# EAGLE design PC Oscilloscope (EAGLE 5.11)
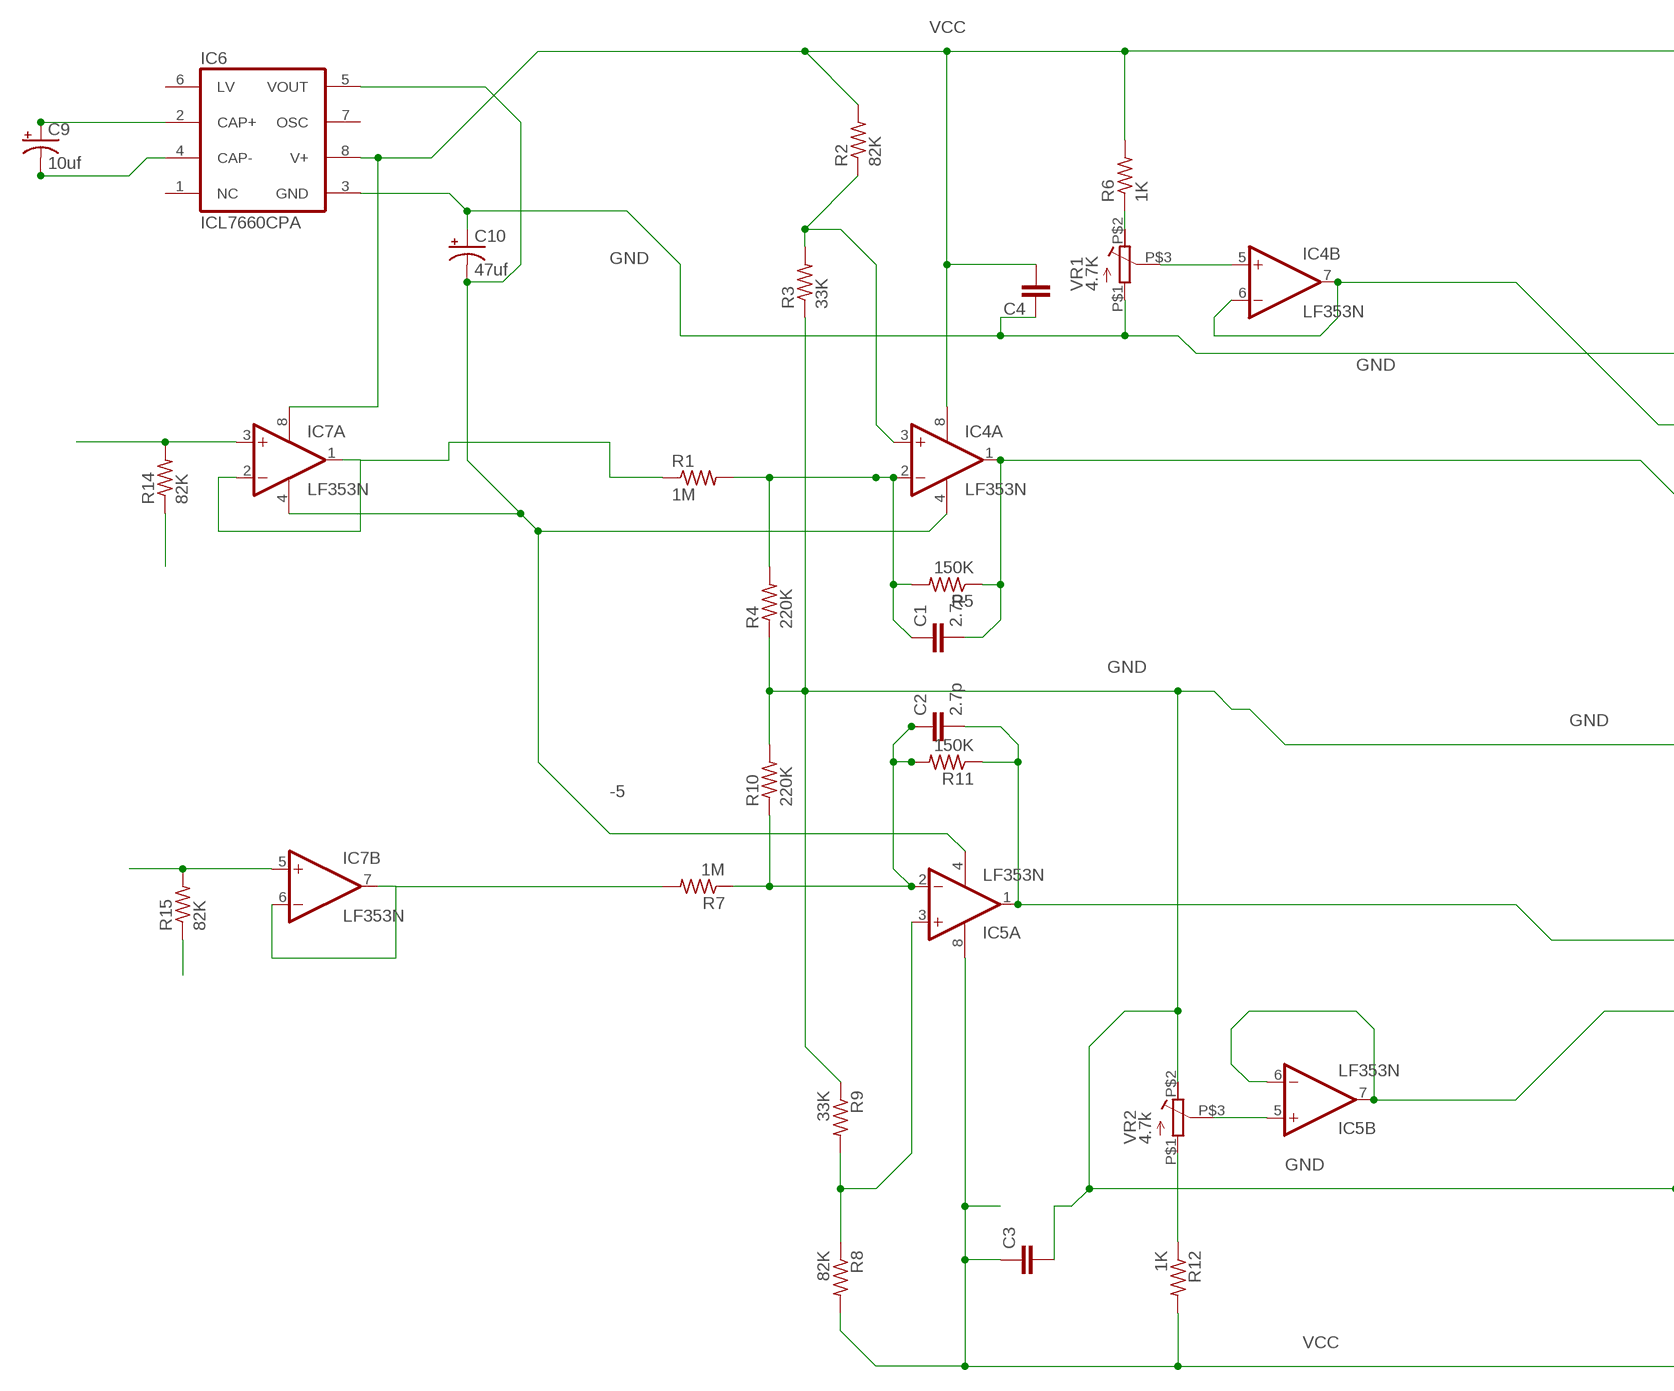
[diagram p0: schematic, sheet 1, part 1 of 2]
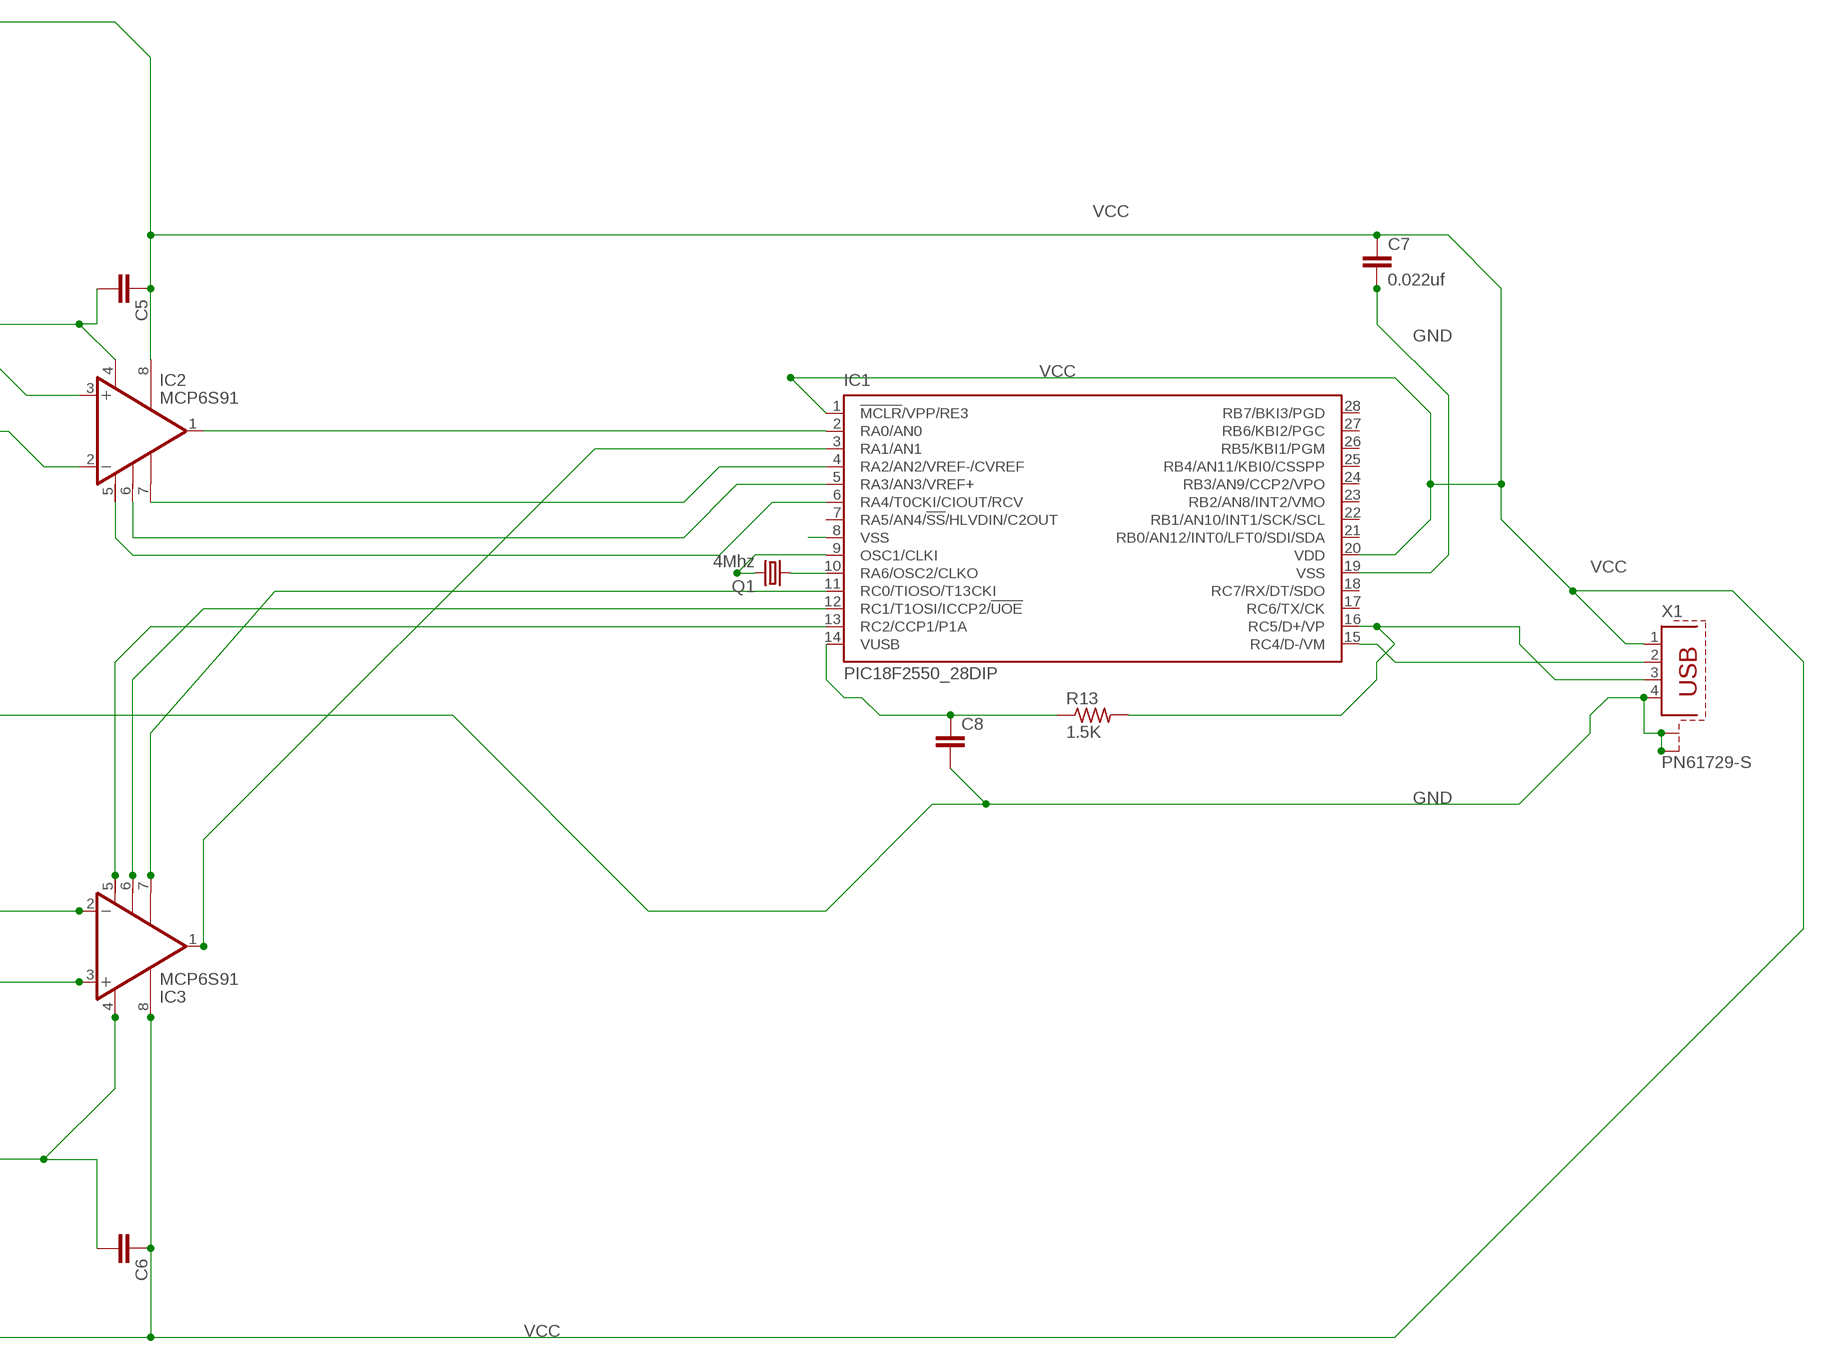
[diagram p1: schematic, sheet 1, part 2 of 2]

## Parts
C1  2.7p  C2,5-3  [C2.5-3]
C2  2.7p  C2,5-3  [C2.5-3]
C3  C7.5/5  [C7.5B5]
C4  C7.5/5  [C7.5B5]
C5  C7.5/5  [C7.5B5]
C6  C7.5/5  [C7.5B5]
C7  0.022uf  C2,5-3  [C2.5-3]
C8  C5/2.5  [C5B2.5]
C9  10uf  CPOL-USE2.5-5  [E2,5-5]
C10  47uf  CPOL-USE2.5-5  [E2,5-5]
IC1  PIC18F2550_28DIP  [DIL28-3]
IC2  MCP6S91  MCP6S  [DIL8]
IC3  MCP6S91  MCP6S  [DIL8]
IC4  LF353N  [DIL08]
IC5  LF353N  [DIL08]
IC6  ICL7660CPA  [DIL08]
IC7  LF353N  [DIL08]
Q1  4Mhz  CRYSTALHC49S  [HC49/S]
R1  1M  R-US_0207/10  [0207/10]
R2  82K  R-US_0207/10  [0207/10]
R3  33K  R-US_0207/10  [0207/10]
R4  220K  R-US_0207/10  [0207/10]
R5  150K  R-US_0207/10  [0207/10]
R6  1K  R-US_0207/10  [0207/10]
R7  1M  R-US_0207/10  [0207/10]
R8  82K  R-US_0207/10  [0207/10]
R9  33K  R-US_0207/10  [0207/10]
R10  220K  R-US_0207/10  [0207/10]
R11  150K  R-US_0207/10  [0207/10]
R12  1K  R-US_0207/10  [0207/10]
R13  1.5K  R-US_0207/10  [0207/10]
R14  82K  R-US_0207/10  [0207/10]
R15  82K  R-US_0207/10  [0207/10]
VR1  4.7K  VARIABLE_RESISTOR  [VAR_RES]
VR2  4.7k  VARIABLE_RESISTOR  [VAR_RES]
X1  PN61729-S  [PN61729-S]

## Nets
-5: C10.- IC4.4(P:V-) IC5.4(P:V-) IC6.5(VOUT) IC7.4(P:V-)
GND: C3.2 C4.1 C5.2 C6.2 C7.2 C8.2 C10.+ IC1.8(VSS) IC1.19(VSS) IC2.4(VSS) IC3.4(VSS) IC6.3(GND) R3.1 R4.1 R9.1 R10.2 R14.1 R15.1 VR1.P$1 VR2.P$2 X1.4 X1.S1 X1.S2
N$1: C2.1 IC5.2(A:-IN) R7.1 R10.1 R11.2
N$2: C2.2 IC3.2(IN) IC5.1(A:OUT) R11.1
N$3: IC5.3(A:+IN) R8.1 R9.2
N$6: C1.1 IC4.2(A:-IN) R1.2 R4.2 R5.2
N$7: C1.2 IC2.2(IN) IC4.1(A:OUT) R5.1
N$9: IC4.3(A:+IN) R2.1 R3.2
N$10: R6.1 VR1.P$2
N$11: IC3.3(REF) IC5.6(B:-IN) IC5.7(B:OUT)
N$13: C9.+ IC6.2(CAP+)
N$14: C9.- IC6.4(CAP-)
N$15: IC4.5(B:+IN) VR1.P$3
N$16: IC2.3(REF) IC4.6(B:-IN) IC4.7(B:OUT)
N$19: R12.1 VR2.P$1
N$20: IC5.5(B:+IN) VR2.P$3
N$21: IC1.10(RA6/OSC2/CLKO) Q1.1
N$23: IC1.2(RA0/AN0) IC2.1(OUT)
N$24: IC1.4(RA2/AN2/VREF-/CVREF) IC2.7(SCK)
N$25: IC1.5(RA3/AN3/VREF+) IC2.6(SI)
N$26: IC1.6(RA4/T0CKI/CIOUT/RCV) IC2.5(CS)
N$27: IC1.13(RC2/CCP1/P1A) IC3.5(CS)
N$28: IC1.12(RC1/T1OSI/ICCP2/!UOE) IC3.6(SI)
N$29: IC1.11(RC0/TIOSO/T13CKI) IC3.7(SCK)
N$30: IC1.3(RA1/AN1) IC3.1(OUT)
N$31: IC1.9(OSC1/CLKI) Q1.2
N$33: C8.1 IC1.14(VUSB) R13.1
N$34: IC1.16(RC5/D+/VP) R13.2 X1.3
N$35: IC1.15(RC4/D-/VM) X1.2
N$41: IC7.3(A:+IN) R14.2
N$42: IC7.1(A:OUT) IC7.2(A:-IN) R1.1
N$43: IC7.5(B:+IN) R15.2
N$44: IC7.6(B:-IN) IC7.7(B:OUT) R7.2
VCC: C3.1 C4.2 C5.1 C6.1 C7.1 IC1.1(!MCLR!/VPP/RE3) IC1.20(VDD) IC2.8(VDD) IC3.8(VDD) IC4.8(P:V+) IC5.8(P:V+) IC6.8(V+) IC7.8(P:V+) R2.2 R6.2 R8.2 R12.2 X1.1
Unconnected: IC1.7(RA5/AN4/!SS!/HLVDIN/C2OUT) IC1.17(RC6/TX/CK) IC1.18(RC7/RX/DT/SDO) IC1.21(RB0/AN12/INT0/LFT0/SDI/SDA) IC1.22(RB1/AN10/INT1/SCK/SCL) IC1.23(RB2/AN8/INT2/VMO) IC1.24(RB3/AN9/CCP2/VPO) IC1.25(RB4/AN11/KBI0/CSSPP) IC1.26(RB5/KBI1/PGM) IC1.27(RB6/KBI2/PGC) IC1.28(RB7/BKI3/PGD) IC6.1(NC) IC6.6(LV) IC6.7(OSC)

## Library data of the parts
C1-C8 = capacitor-wima:C: CAPACITOR
C9 C10 = rcl:CPOL-US: POLARIZED CAPACITOR, American symbol
IC1 = microchip:PIC18F2*_28: USB Microcontrollers with nanoWatt Technology High-Performance, Enhanced Flash, 28/40/44-Pin, Source: http://ww1.microchip.com/downloads/en/devicedoc/39632c.pdf; MF: MICROCHIP; MPN: PIC18F2550-I/SP; OC_FARNELL: 1523822; OC_NEWARK: 80K6054
IC2 IC3 = microchip:MCP6S**
IC4 IC5 IC7 = linear:LF353: OP AMP
IC6 = maxim:ICL7660CPA: VOLTAGE CONVERTER; MF: INTERSIL; MPN: ICL7660CPA; OC_FARNELL: 1018170; OC_NEWARK: 06F7441
Q1 = crystal:CRYSTAL: CRYSTAL; OC_FARNELL: 1667008; OC_NEWARK: unknown
R1-R15 = rcl:R-US_: RESISTOR, American symbol
VR1 VR2 = mycustom:VARIABLE_RESISTOR: Variable Resistor A Gernal purpose varible resistor
X1 = con-berg:PN61729-S: BERG USB connector; OC_FARNELL: unknown; OC_NEWARK: unknown

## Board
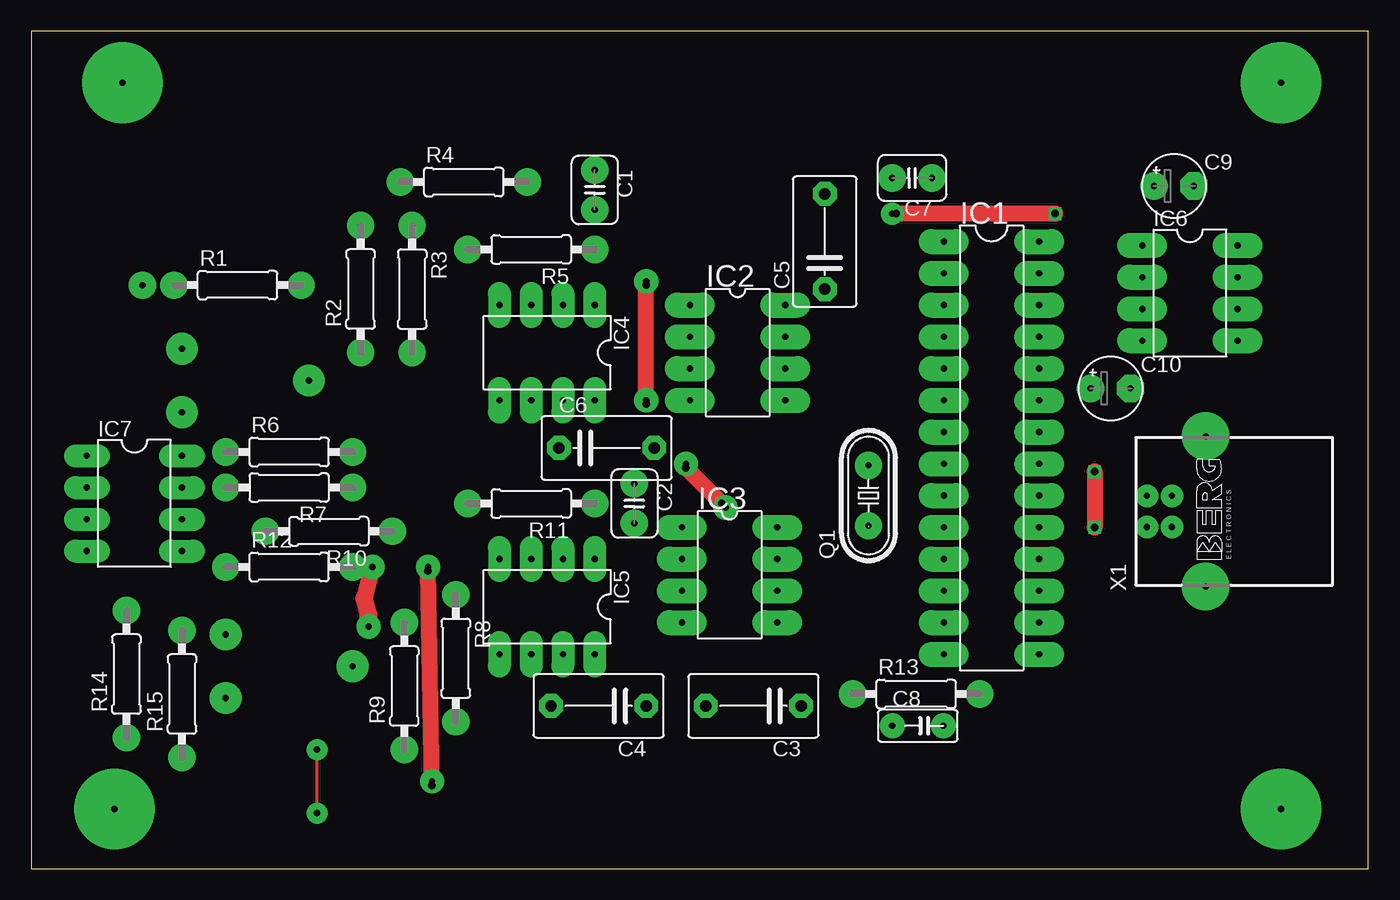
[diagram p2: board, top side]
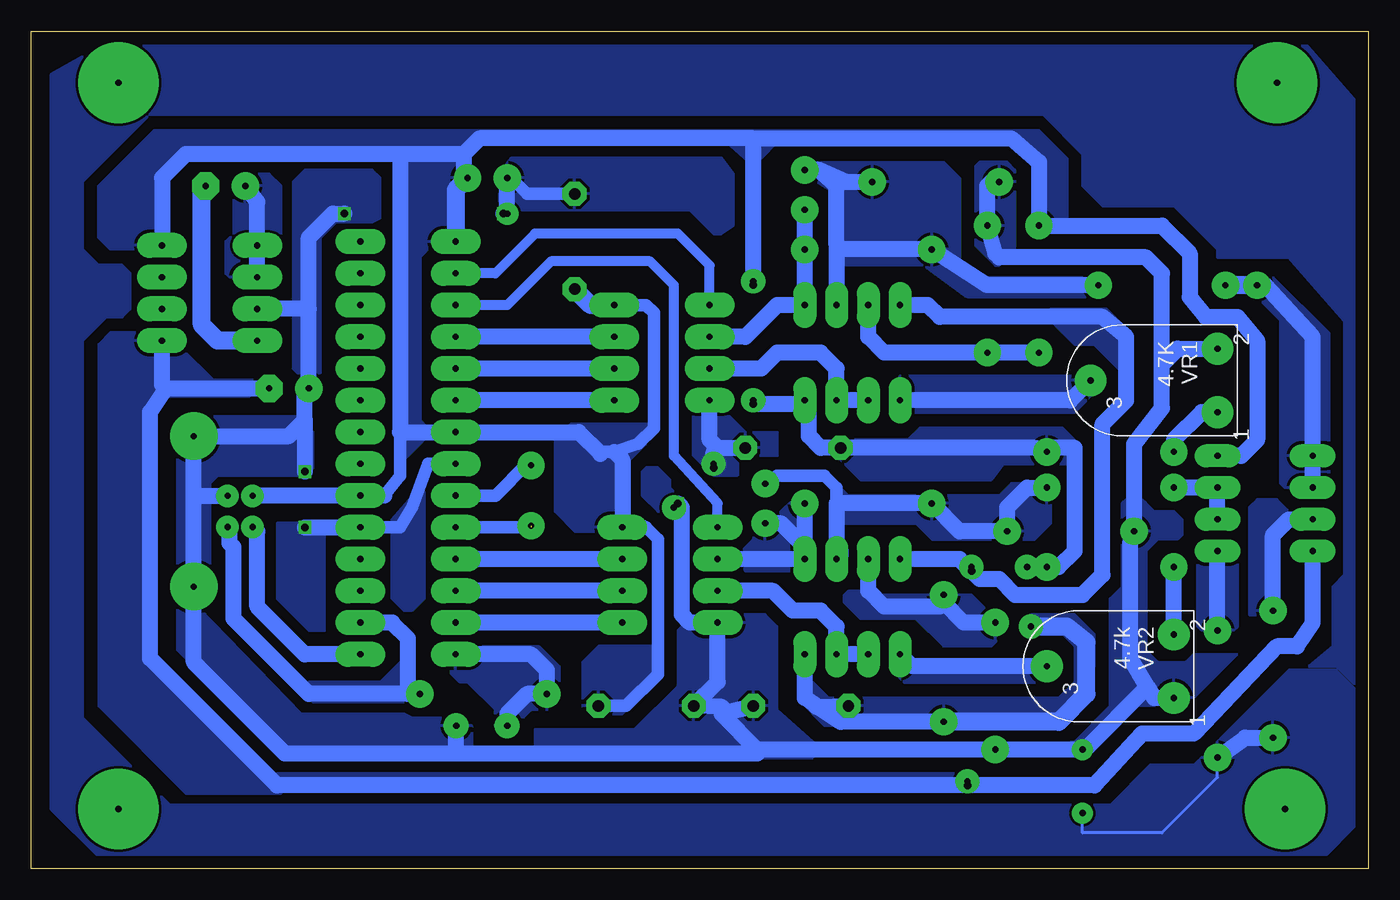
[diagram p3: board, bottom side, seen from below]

Size 106.98 x 66.98 mm. Coordinates in mm from the lower left corner, seen from the top.
Outline: 0,0 106.98,0 106.98,66.98 0,66.98 0,0
Copper layers (1*16): Top 0.035mm / dielectric 1.5mm / Bottom 0.035mm
Design rules "default": minimum track width 10mil, minimum drill 24mil, track to track 8mil, track to pad 8mil, pad to pad 8mil, via to via 8mil, smd to smd 8mil, copper to edge 40mil, drill to drill 8mil, minimum pad ring 10mil, minimum via ring 8mil, stop-mask expansion 4mil, vias tented up to drill 0mil, thermal gap 10mil

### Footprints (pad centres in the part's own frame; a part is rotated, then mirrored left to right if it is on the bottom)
C2.5-3 = drill 0.5 pad 2.184 round: 1 -1.587,0; 2 1.587,0
C7.5B5 = drill 0.914 pad 1.905 octagon: 1 -3.81,0; 2 3.81,0
C5B2.5 = drill 0.5 pad 2 round: 1 -2.54,0; 2 1.54,0
E2,5-5 = drill 0.5 pad 2.184 round: + -1.587,0 | drill 0.5 pad 2.184 octagon: - 1.587,0
DIL28-3 = drill 0.5 pad 2 long: 1 -16.51,-3.81; 2 -13.97,-3.81; 3 -11.43,-3.81; 4 -8.89,-3.81; 5 -6.35,-3.81; 6 -3.81,-3.81; 7 -1.27,-3.81; 8 1.27,-3.81; 9 3.81,-3.81; 10 6.35,-3.81; 11 8.89,-3.81; 12 11.43,-3.81; 13 13.97,-3.81; 14 16.51,-3.81; 15 16.51,3.81; 16 13.97,3.81; 17 11.43,3.81; 18 8.89,3.81; 19 6.35,3.81; 20 3.81,3.81; 21 1.27,3.81; 22 -1.27,3.81; 23 -3.81,3.81; 24 -6.35,3.81; 25 -8.89,3.81; 26 -11.43,3.81; 27 -13.97,3.81; 28 -16.51,3.81
DIL8 = drill 0.5 pad 2 long: 1 -3.81,-3.81; 2 -1.27,-3.81; 3 1.27,-3.81; 4 3.81,-3.81; 5 3.81,3.81; 6 1.27,3.81; 7 -1.27,3.81; 8 -3.81,3.81
DIL08 = drill 0.5 pad 1.85 long: 1 -3.81,-3.81; 2 -1.27,-3.81; 3 1.27,-3.81; 4 3.81,-3.81; 5 3.81,3.81; 6 1.27,3.81; 7 -1.27,3.81; 8 -3.81,3.81
DIL08' = drill 0.5 pad 2 long: 1 -3.81,-3.81; 2 -1.27,-3.81; 3 1.27,-3.81; 4 3.81,-3.81; 5 3.81,3.81; 6 1.27,3.81; 7 -1.27,3.81; 8 -3.81,3.81
HC49/S = drill 0.5 pad 2.184 round: 1 -2.413,0; 2 2.413,0
0207/10 = drill 0.5 pad 2.184 round: 1 -5.08,0; 2 5.08,0
VAR_RES = drill 0.5 pad 2.54 round: P$1 -2.54,3.81; P$2 2.54,3.81; P$3 0,-6.35
PN61729-S = drill 0.5 pad 1.8 round: 1 1.25,4.71; 2 -1.25,4.71; 3 -1.25,2.71; 4 1.25,2.71 | drill 0.5 pad 3.81 round: S1 -6.02,0; S2 6.02,0

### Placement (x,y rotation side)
C1  45.09,54.29 270 top
C2  48.26,29.21 270 top
C3  57.78,13.02 180 top
C4  45.4,13.02 180 top
C5  63.5,50.16 90 top
C6  46.04,33.66 0 top
C7  70.48,55.24 180 top
C8  71.44,11.43 0 top
C9  91.44,54.61 0 top
C10  86.36,38.42 0 top
IC1  76.83,33.66 270 top
IC2  56.52,41.27 270 top
IC3  55.88,23.5 270 top
IC4  41.27,41.27 180 top
IC5  41.27,20.95 180 top
IC6  ICL7660CPA  [DIL08']  92.71,46.04 270 top
IC7  8.26,29.21 270 top
Q1  66.99,29.84 90 top
R1  16.51,46.67 0 top
R2  26.35,46.35 90 top
R3  30.48,46.35 270 top
R4  34.61,54.93 0 top
R5  40.01,49.53 180 top
R6  20.64,33.34 0 top
R7  20.64,30.48 180 top
R8  33.97,16.83 270 top
R9  29.84,14.61 90 top
R10  23.81,26.99 180 top
R11  40.01,29.21 180 top
R12  20.64,24.13 0 top
R13  70.8,13.97 0 top
R14  7.62,15.56 90 top
R15  12.06,13.97 90 top
VR1  15.88,39.05 270 bottom
VR2  19.37,16.19 270 bottom
X1  93.98,28.57 90 top

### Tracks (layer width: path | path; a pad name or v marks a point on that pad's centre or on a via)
-5  (via drill 0.6)
  Top 1.27: v32.07,6.67 v31.75,23.81
  Bottom 1.27: IC4.4 35.24,45.09 34.29,44.13 21.27,44.13 19.37,42.55 19.37,37.47 21.27,35.56 21.27,23.5 22.86,21.91 28.26,21.91 29.53,23.18 31.11,23.18 v31.75,23.81 | v31.75,23.81 32.7,24.77 | 32.7,24.77 IC5.4 | v31.75,23.81 32.7,24.77 | 96.2,38.42 C10.- | 96.2,38.42 97.47,36.51 97.47,16.83 87.31,6.67 v32.07,6.67 21.91,6.67 18.1,10.79 13.97,10.79 7.3,17.78 5.71,17.78 4.45,19.68 IC7.4 | IC6.5 96.52,38.73 96.2,38.42
  pour Bottom: 89.22,39.05 92.39,39.05 94.93,41.59 94.93,42.55 95.25,42.86 100.65,42.86 101.6,41.91 101.6,13.02 94.61,6.03 87,6.03 86.36,6.67 87,6.67 97.47,17.14 97.47,37.47 97.16,37.78 89.53,37.78 89.22,38.1
  pour Bottom: 87.31,7.62 33.02,7.62 31.75,6.35 87,6.35 87.95,7.3
  pour Bottom: 19.05,40.01 20,40.01 21.91,41.91 23.5,41.91 25.4,43.81 25.4,44.77 20.95,44.77 19.05,42.86
GND  (via drill 0.5 pad 1.68, 0.5 pad 1.93, 0.6)
  Top 0.254: v22.86,4.45 v22.86,9.53
  Top 1.27: v81.92,52.39 v69.22,52.39 | v55.24,29.21 v52.39,32.07 | v85.09,31.75 v85.09,27.3
  Bottom 0.254: VR2.P$2 18.1,13.65 18.41,13.97 v22.86,9.53 | v22.86,4.45 22.86,2.86 16.51,2.86 12.06,7.3 R15.1
  Bottom 1.016: IC1.8 75.25,32.38 76.52,28.89 77.47,27.3 IC1.19 | C7.2 68.58,55.24 67.31,53.98 C5.2
  Bottom 1.27: VR2.P$2 17.14,13.65 17.68,14.54 | 17.68,14.54 19.05,16.83 19.05,26.04 R10.2 18.73,33.97 16.51,36.83 16.51,40.32 | 48.58,9.53 R9.1 v22.86,9.53 22.69,9.53 17.68,14.54 | 48.58,9.53 48.9,9.53 51.75,12.38 51.3,12.49 | R4.1 30.16,54.93 30.48,54.61 R3.1 29.84,49.21 29.53,48.9 17.78,48.9 16.51,47.62 16.51,40.32 | VR1.P$1 15.24,41.59 16.51,40.32 | X1.S1 | X1.S1 93.98,16.51 86.68,9.21 73.03,9.21 | 73.03,9.21 48.9,9.21 48.58,9.53 | 51.3,12.49 C4.1 | C7.2 68.9,52.7 v69.22,52.39 | IC3.4 53.66,19.68 | IC3.4 52.07,14.92 C3.2 51.75,12.94 51.3,12.49 | IC2.4 52.7,34.29 52.07,33.66 | 52.07,33.66 C6.2 49.85,33.34 | IC3.4 54.29,19.68 54.93,20.32 54.93,28.89 v55.24,29.21 | v52.39,32.07 v52.39,32.38 52.39,33.34 52.07,33.66 | C8.2 72.98,9.26 73.03,9.21 | v81.92,52.39 82.87,52.39 84.77,50.48 84.77,44.77 | 84.77,44.77 IC6.3 | 84.77,44.77 C10.+ 85.09,38.1 85.09,35.88 | X1.S1 93.98,29.84 | 93.98,29.84 X1.S2 86.37,34.59 85.09,35.88 | v85.09,27.3 IC1.19 | 85.09,35.88 v85.09,31.75 | X1.4 93.96,29.82 93.98,29.84 | R14.1 9.84,10.48 R15.1
  pour Bottom: 82.87,27.62 87.31,27.62 87.31,21.59 84.77,19.05 83.5,19.05 83.5,26.99
  pour Bottom: 50.8,55.56 51.75,56.83 68.58,56.83 69.53,55.56 69.53,53.34 68.9,52.7 54.29,52.7 52.39,50.8 51.75,50.8 50.8,51.44
  pour Bottom: 48.26,20.32 53.98,20.32 55.24,19.05 55.24,14.61 58.74,11.11 66.67,11.11 66.67,8.89 44.45,8.89 44.45,10.16 47.31,12.7 47.31,19.37
  pour Bottom: 53.98,37.47 52.39,37.47 49.85,34.92 47.31,34.92 47.31,33.02 50.16,33.02 50.48,32.7 50.48,31.43 52.39,31.43 53.98,33.02
  pour Bottom: 75.56,30.16 75.56,21.59 76.52,20.64 77.15,20.64 78.11,21.59 78.11,27.94 76.2,30.16
  pour Bottom: 93.34,21.91 93.66,20.95 85.41,12.38 77.15,12.38 76.52,12.06 72.39,12.06 71.75,11.43 71.75,9.53 72.39,8.89 87,8.89 94.3,16.19 94.3,16.51 95.25,17.46 95.25,35.56 94.61,36.2 85.72,36.2 84.45,34.92 84.45,32.07 85.09,31.43 92.08,31.43 92.71,30.8 92.71,22.54
  pour Bottom: 79.06,52.07 79.06,55.24 79.69,55.88 85.09,55.88 86.04,54.93 86.04,40.01 85.09,39.05 84.45,39.05 83.82,39.69 83.82,50.48 82.55,51.75 79.69,51.75
  pour Bottom: 28.89,56.52 31.11,56.52 31.43,56.2 31.43,49.85 29.84,48.26 29.53,48.26 28.26,49.53 28.26,55.88
  pour Bottom: 2.54,15.88 6.35,15.88 13.97,8.26 17.46,8.26 20.64,5.08 95.89,5.08 102.87,12.06 102.87,42.23 100.97,44.13 99.69,44.13 99.06,44.77 99.06,47.62 99.69,48.26 101.6,48.26 102.87,49.53 102.87,54.93 97.47,60.33 26.04,60.33 22.86,57.15 22.86,54.61 21.27,53.02 15.56,53.02 12.06,49.53 12.06,48.9 6.35,48.9 1.91,43.81 1.91,23.5 2.86,22.54 2.86,17.78 4.76,16.19 2.54,16.19 0.95,14.61 0.32,14.61 0.64,60.96 5.08,66.04 100.97,66.04 105.41,63.5 105.41,4.76 101.6,0.95 3.49,0.95 0.95,3.49 0.95,14.29
  pour Bottom: 18.73,29.53 18.1,29.53 17.78,29.21 17.46,28.89 17.14,28.57 15.56,28.57 14.92,27.94 14.92,26.67 15.24,26.35 16.83,26.35 17.78,25.4 17.78,17.46 16.83,16.51 14.92,16.51 14.29,15.88 14.29,13.34 14.61,13.02 18.41,13.02 21.91,9.53 23.18,9.53 23.81,10.16 23.5,10.16 20.64,13.02 20.64,21.59 19.68,22.54 19.68,29.21 19.37,29.53
  pour Bottom: 17.14,16.51 14.61,16.51 13.97,17.14 10.48,17.14 14.61,13.02 17.46,13.02
N$1
  Bottom 1.016: 47.94,30.8 47.31,31.43 43.5,31.43 42.55,30.48 42.55,29.21
  Bottom 1.27: R7.1 27.3,30.48 28.89,28.89 R10.1 32.7,26.99 R11.2 42.55,29.21 42.55,25.72 42.23,25.4 42.23,25.08 IC5.2 | 47.94,30.8 C2.1
  pour Bottom: 26.04,30.8 28.57,30.8 29.53,29.84 41.59,29.84 42.23,30.48 42.55,30.48 42.86,30.16 42.86,27.94 42.55,27.62 36.2,27.62 34.92,26.35 26.67,26.35 25.4,27.62 25.4,30.16
N$2
  Bottom 1.27: 45.09,25.72 IC5.1 IC3.2 | 45.09,25.72 R11.1 | C2.2 46.99,27.62 45.09,25.72
  pour Bottom: 45.4,29.84 45.72,29.84 47.31,28.26 48.9,28.26 49.21,27.94 49.21,26.35 50.16,25.4 50.16,24.13 49.85,23.81 45.09,23.81 45.09,29.21 44.77,29.53
N$3
  Bottom 1.27: 33.97,21.27 R8.1 | 33.97,21.27 32.38,19.68 R9.2 | IC5.3 40.01,22.23 38.73,20.95 34.29,20.95 33.97,21.27
  pour Bottom: 39.05,21.91 31.75,21.91 29.84,20 29.84,18.1 30.16,17.78 33.97,17.78 36.2,20 40.64,20 41.91,21.27 41.91,21.91 41.59,22.23 40.32,22.23
N$4  (via drill 0.5 pad 1.68)
  other vias: 22.86,4.45
N$5  (via drill 0.5 pad 1.93)
  other vias: 32.07,6.99
N$6
  Bottom 1.27: 42.55,49.85 IC4.2 | 42.55,49.85 42.55,54.61 44.05,55.93 | 44.05,55.93 C1.1 | 42.55,49.85 42.23,49.53 R5.2 30.48,46.67 R1.2 | R4.2 41.78,54.93 44.05,55.93
  pour Bottom: 45.4,56.52 33.97,56.52 32.7,55.24 32.7,48.58 31.43,47.31 21.91,47.31 21.91,45.72 32.07,45.72 35.56,48.26 42.23,48.26 42.55,48.58 42.55,53.98 45.09,55.56 45.72,55.56 45.72,56.2
N$7
  Bottom 1.27: IC2.2 49.85,42.55 47.31,45.09 IC4.1 R5.1 C1.2
N$8  (via drill 0.5 pad 2.18)
  other vias: 8.89,46.67
N$9
  Bottom 1.27: R2.1 R3.2 38.73,41.27 40.01,42.55 IC4.3
N$10
  Bottom 1.27: VR1.P$2 13.34,36.51 15.56,34.29 R6.1
N$11
  Bottom 1.27: IC5.6 IC5.7 42.55,19.37 43.81,20.64 46.04,20.64 47.62,22.23 IC3.3
N$12  (via drill 0.5 pad 1.78)
  other vias: 68.9,52.39
N$13
  Bottom 1.27: IC6.2 88.9,53.34 C9.+
  pour Bottom: 87.95,55.56 90.49,55.56 90.81,55.24 90.81,50.8 91.44,50.16 91.44,47.62 90.49,46.67 87.63,46.67 87,47.31 87,54.61
N$14
  Bottom 1.422: IC6.4 92.08,42.23 93.34,43.5 93.34,54.61 C9.-
N$15
  Bottom 1.27: VR1.P$3 23.81,37.47 IC4.5
  pour Bottom: 22.54,39.37 37.47,39.37 37.78,39.05 37.78,36.83 37.47,36.51 23.5,36.51 21.59,38.42
N$16
  Bottom 1.27: 53.02,39.69 IC2.3 48.58,40.01 47.31,41.27 43.81,41.27 42.55,40.01 IC4.7 IC4.6
N$17  (via drill 0.5 pad 1.93)
  other vias: 31.75,24.13
N$18  (via drill 0.5 pad 1.93)
  other vias: 55.56,28.89
N$19
  Bottom 1.27: VR2.P$1 R12.1
N$20
  Bottom 1.27: VR2.P$3 36.51,16.19 IC5.5
  pour Bottom: 25.72,16.51 36.83,16.51 37.47,17.14 38.1,17.14 38.1,15.88 37.15,14.92 26.04,14.92 25.4,15.56
N$21  (1 unrouted)
  Bottom 1.016: IC1.10 66.99,27.3 66.67,27.62
N$22
  Bottom 1.422: 8.57,46.67 11.75,46.67
N$23
  Bottom 0.813: IC2.1 52.7,48.26 55.24,50.8 66.67,50.8 69.85,47.62 IC1.2
N$24
  Bottom 1.27: IC2.7 IC1.4
N$25
  Bottom 1.27: IC2.6 IC1.5
N$26
  Bottom 1.27: IC2.5 IC1.6
N$27
  Bottom 1.27: IC3.5 IC1.13
N$28
  Bottom 1.27: IC3.6 IC1.12
N$29
  Bottom 1.27: IC3.7 IC1.11
N$30
  Bottom 0.813: IC3.1 52.07,29.21 55.56,33.02 55.56,46.67 57.47,48.58 65.41,48.58 68.9,45.09 IC1.3
N$31
  Bottom 1.016: IC1.9 69.85,29.84 67.31,32.38 66.8,32.38 Q1.2
N$32  (via drill 0.5 pad 6.45)
  other vias: 6.67,4.76
N$33
  Bottom 1.27: C8.1 68.9,12.38 67.31,13.97 R13.1 65.72,15.88 66.99,17.14 IC1.14
  pour Bottom: 73.34,17.78 66.36,17.78 64.77,16.19 64.77,13.34 65.41,12.7 66.99,12.7 68.26,11.43 68.26,11.11 68.58,10.79 69.22,10.79 69.85,11.43 69.85,12.7 72.07,14.92 72.71,14.92 73.34,15.56
N$34
  Bottom 1.27: IC1.16 78.11,19.68 76.83,18.41 76.83,13.97 | R13.2 84.77,13.97 90.81,20 90.81,25.72 91.12,26.04 91.12,27.18 X1.3
  pour Bottom: 76.83,16.83 77.15,16.83 79.06,14.92 84.77,14.92 84.77,13.65 84.45,13.34 76.52,13.34 76.2,13.65
N$35
  Bottom 1.27: IC1.15 85.09,17.14 88.9,20.95 88.9,26.95 X1.2
N$36  (via drill 0.5 pad 6.45)
  other vias: 100.01,4.76
N$37  (via drill 0.5 pad 6.45)
  other vias: 7.3,62.87
N$38  (via drill 0.5 pad 6.45)
  other vias: 100.01,62.87
N$40
  pour Bottom: 54.93,28.89 54.93,29.53 55.88,30.48 55.88,31.11 56.83,32.07 57.78,32.07 58.1,31.75 58.1,29.84 56.83,28.57 56.2,28.57 55.56,27.94
N$41
  Bottom 1.27: IC7.3 6.35,27.94 7.62,26.67 R14.2
  pour Bottom: 5.08,27.94 5.71,27.94 7.3,29.53 8.89,29.53 9.53,28.89 9.53,20.32 7.3,20.32 6.67,20.95 7.3,21.59 7.3,26.35 6.67,26.99
N$42
  Bottom 1.27: IC7.2 IC7.1 4.45,42.55 8.26,46.67 R1.1
  pour Bottom: 11.75,47.31 7.62,47.31 3.17,42.86 3.17,30.8 3.81,30.16 6.35,30.16 6.99,30.8 6.99,43.81 9.21,46.04 11.75,46.04 12.06,46.35
N$43
  Bottom 1.27: R15.2 IC7.5
  pour Bottom: 10.48,25.4 10.48,19.37 10.79,19.05 13.02,18.73 13.65,19.37 13.65,24.77 13.02,25.4
N$44
  Bottom 1.27: IC7.6 IC7.7 R7.2
VCC  (via drill 0.5 pad 1.93, 0.6)
  Top 1.27: 26.67,21.59 v27.3,24.13 | v49.21,37.15 v49.21,37.47 v49.21,46.67
  Top 1.422: 26.67,21.59 26.99,20.32 v26.99,19.37
  Bottom 1.016: 78.74,29.84 77.47,31.43 77.47,34.29 77.31,35.08 77.47,34.92 | IC2.8 57.78,45.09 57.15,44.45 57.15,35.24 58.42,33.97 60.33,33.34 61.28,33.34 61.44,33.18 | 58.1,27.3 57.78,27.3 56.83,26.35 56.83,15.56 59.37,13.02 C3.1
  Bottom 1.27: X1.1 80.67,29.82 IC1.20 78.74,29.84 | R8.2 42.23,11.75 44.35,13.16 | 44.35,13.16 45.09,13.65 IC5.8 45.13,17.1 | 26.35,52.07 26.35,56.52 28.57,58.42 49.21,58.42 | 26.35,52.07 R2.2 | C7.1 72.39,55.56 72.39,57.15 | 77.47,34.92 63.18,34.92 61.44,33.18 | C4.2 44.13,12.94 44.35,13.16 | R12.2 24.77,24.13 23.5,25.4 23.5,33.66 25.4,33.66 R6.2 26.67,33.66 C6.1 43.81,33.66 44.77,34.61 44.77,36.83 | 44.77,36.83 44.77,37.15 IC4.8 | 44.77,36.83 45.09,37.15 v49.21,37.15 | 49.21,58.42 v49.21,46.99 v49.21,46.67 | 77.47,34.92 | 77.47,57.15 77.47,34.92 | 77.31,35.08 77.47,34.92 | 58.1,27.3 IC3.8 59.69,32.7 60.33,33.34 | IC6.8 96.52,55.24 94.61,57.15 77.47,57.15 | 49.21,58.42 71.12,58.42 72.39,57.15 | 72.39,57.15 77.47,57.15 | IC7.8 10.16,33.02 8.89,34.29 8.89,42.23 10.48,44.13 13.02,44.13 14.29,45.72 14.29,49.21 16.51,51.44 25.72,51.44 26.35,52.07
  Bottom 1.422: IC1.1 73.03,54.29 C7.1 | IC2.8 62.23,45.09 C5.1 | v27.3,24.13 R12.2 | R8.2 24.77,11.75 22.54,13.97 22.54,18.1 24.13,19.37 v26.99,19.37
  pour Bottom: 97.16,49.53 100.65,49.53 101.6,50.48 101.6,54.61 97.16,59.05 26.35,59.05 24.13,56.83 24.13,52.07 24.45,51.75 26.67,51.75 26.67,56.52 28.57,58.42 71.12,58.42 72.39,57.15 95.25,57.15 96.52,55.88 96.52,49.53 96.84,49.21
  pour Bottom: 57.47,35.56 63.82,35.56 65.09,34.29 65.09,28.57 63.5,26.99 60.01,26.99 59.37,27.62 59.37,32.38 57.78,33.97 58.1,34.29 57.15,35.24
  pour Bottom: 23.18,32.07 23.18,33.97 24.45,35.24 35.88,35.24 36.83,34.29 42.23,34.29 42.55,33.97 42.55,33.02 40.64,31.11 30.16,31.11 29.21,32.38 23.5,32.38
  pour Bottom: 44.77,14.92 44.45,14.92 43.18,13.65 23.81,13.65 23.5,13.34 23.5,12.38 24.45,11.43 43.5,11.43 45.4,13.34
  pour Bottom: 56.83,17.78 61.59,17.78 62.87,16.51 62.87,12.7 62.55,12.38 59.69,12.38 56.52,15.56 56.52,17.46
  pour Bottom: 73.03,49.85 74.93,49.85 75.88,48.9 75.88,35.88 75.25,35.24 75.25,34.61 77.15,32.7 77.47,32.7 77.79,33.34 77.79,56.83 76.52,58.42 73.34,58.42 72.71,57.78 72.71,52.7
  pour Bottom: 21.91,18.73 23.5,20.32 26.99,20.32 27.62,19.68 27.62,19.05 27.3,18.73 24.45,18.73 23.5,17.78 23.5,14.92 24.77,13.65 24.77,11.75 24.13,11.75 22.23,13.65 22.23,15.88 21.91,16.19
  pour Bottom: 46.67,58.74 49.21,56.2 52.07,58.74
